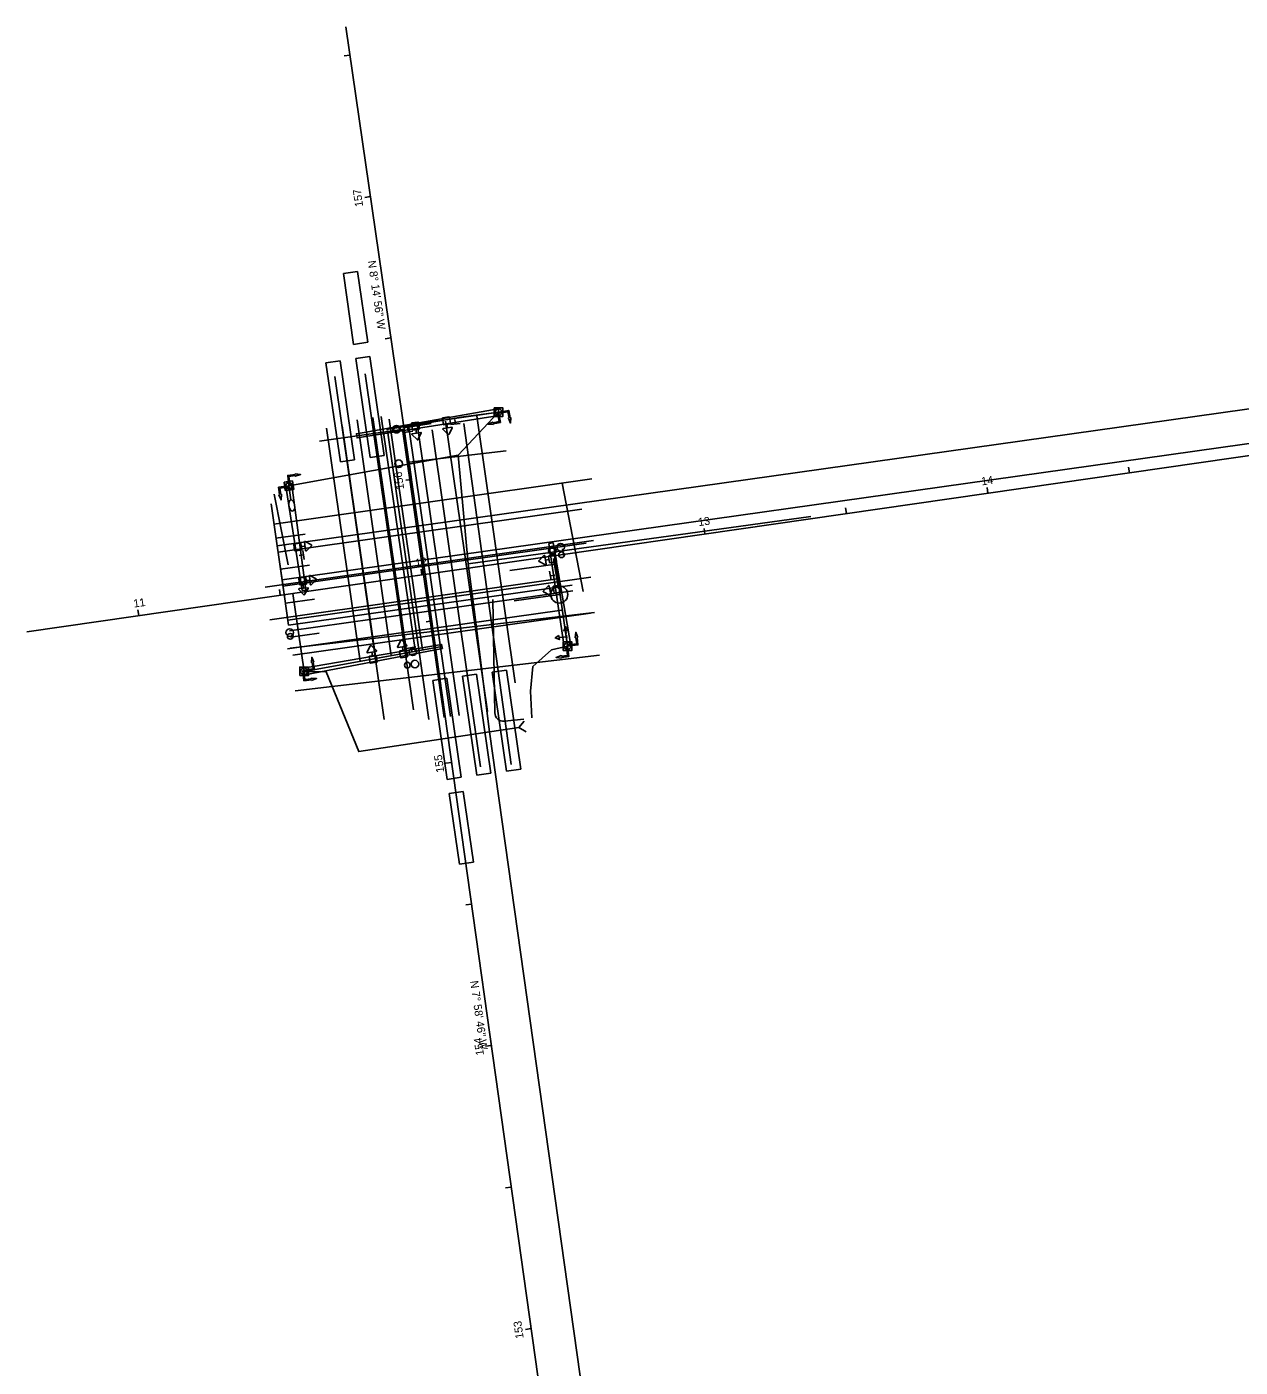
# Model space of a CAD drawing. Extents: x 1827063 to 1831280, y 711192 to 712800.
# Drawn here: x 1827917.1 to 1828341.4, y 712025.4 to 712494.3 of the extents above; entities that cross this region are included whole.
import ezdxf

# ---------------------------------------------------------------- set-up
doc = ezdxf.new("R2010")
doc.units = 0
for name, color, linetype in [('BR_P_Gen_Joint_Filler', 7, 'Continuous'), ('BR_P_Sub_Centerline', 7, 'Continuous'), ('Default', 7, 'Continuous'), ('DR_P_Cells', 7, 'Continuous'), ('DR_P_Storm_Sewer', 7, 'Continuous'), ('LT_P_Luminaires', 7, 'Continuous'), ('PV_P_Walk', 7, 'Continuous'), ('SC_Scratch6', 7, 'Continuous'), ('SG_P_Wiring', 7, 'Continuous'), ('SG_X_Detection', 7, 'Continuous'), ('SG_X_Interconnect_Cable', 7, 'Continuous'), ('TX_P_20', 7, 'Continuous'), ('UT_P_Water', 7, 'Continuous'), ('UT_P_Water_Text', 7, 'Continuous'), ('UT_X_Misc_Cells', 7, 'Continuous'), ('VG_X_Cells', 7, 'Continuous')]:
    doc.layers.add(name, color=color, linetype=linetype)

# ---------------------------------------------------------------- blocks, each defined once
blk = doc.blocks.new('SGN1P')
at = {"layer": 'UT_X_Misc_Cells'}
for p, q in [((0, 0), (-0.08, 0)), ((0, 0.08), (0, -0.08))]:
    blk.add_line(p, q, dxfattribs=at)
blk = doc.blocks.new('Sighead')
at = {"layer": 'Default'}
for p, q in [((-0.03, 0.975), (-0.335, 0.569)), ((0.335, 0.569), (0.03, 0.975)), ((-0.305, 0.508), (0.305, 0.508)), ((-0.254, -0.216), (-0.254, 0.216)), ((-0.216, 0.254), (0.216, 0.254)), ((0, 0.508), (0, 0.254)), ((0.254, 0.216), (0.254, -0.216)), ((0.216, -0.254), (-0.216, -0.254))]:
    blk.add_line(p, q, dxfattribs=at)
for centre, start, end in [((0, 0.953), 36.8699, 143.1301), ((-0.305, 0.546), 143.1301, 270), ((-0.216, 0.216), 90, 180), ((0.216, 0.216), 0, 90), ((0.305, 0.546), 270, 36.8699), ((-0.216, -0.216), 180, 270), ((0.216, -0.216), 270, 0)]:
    blk.add_arc(centre, 0.0381, start, end, dxfattribs=at)
blk = doc.blocks.new('SPOLE')
at = {"layer": 'DR_P_Cells'}
blk.add_lwpolyline([(-0.075, -0.075), (0.075, -0.075), (0.075, 0.075), (-0.075, 0.075)], close=True, dxfattribs=at)
blk.add_circle((0, 0), 0.06, dxfattribs=at)

msp = doc.modelspace()

# ---------------------------------------------------------------- linework, layer by layer
at = {"layer": 'BR_P_Gen_Joint_Filler'}
for p, q in [((1828044.52, 712274.33), (1828032.59, 712356.83)), ((1828049.96, 712275.12), (1828038.03, 712357.61)), ((1828052.93, 712275.55), (1828041, 712358.04)), ((1828057.4, 712355.81), (1828042.89, 712353.41)), ((1828055.44, 712276.31), (1828043.76, 712357.03)), ((1828068.96, 712357.7), (1828057.4, 712355.81)), ((1828063.52, 712356.41), (1828078.1, 712254.78)), ((1828082.02, 712359.5), (1828068.96, 712357.7)), ((1828074.39, 712358.22), (1828087.78, 712264.83)), ((1828033.67, 712272.37), (1828021.87, 712353.92)), ((1828039.11, 712273.16), (1828027.31, 712354.71)), ((1828043.2, 712353.03), (1828057.69, 712251.99)), ((1828062.99, 712252.68), (1828048.47, 712353.53)), ((1828050.7, 712354.28), (1828065.22, 712253)), ((1828053.66, 712354.77), (1828068.19, 712253.43)), ((1828003.47, 712320.37), (1828114.59, 712336.14)), ((1828104.23, 712334.63), (1828111.66, 712296.73)), ((1828003.59, 712330.85), (1828008.39, 712306.15)), ((1828004.91, 712310.47), (1828111.11, 712325.54)), ((1828000.42, 712298.29), (1828115.25, 712314.57)), ((1828004.19, 712315.42), (1828014.37, 712316.86)), ((1828006.63, 712298.59), (1828112.68, 712313.64)), ((1828005.77, 712304.53), (1828015.91, 712305.97)), ((1828085.97, 712304.11), (1828101.89, 712306.37)), ((1828002.03, 712286.9), (1828102.63, 712301.17)), ((1828008.35, 712286.72), (1828114.25, 712301.74)), ((1828087.48, 712293.47), (1828103.4, 712295.72)), ((1828007.49, 712292.65), (1828017.6, 712294.09)), ((1828008.24, 712276.67), (1828104.12, 712290.27)), ((1828010.13, 712274.46), (1828114.22, 712289.23)), ((1828009.21, 712280.78), (1828019.28, 712282.21))]:
    msp.add_line(p, q, dxfattribs=at)
msp.add_circle((1828103.24, 712295.7), 3, dxfattribs=at)
at = {"layer": 'BR_P_Sub_Centerline'}
for p, q in [((1828009.09, 712276.96), (1828115.54, 712289.43)), ((1828010.84, 712262.06), (1828117.28, 712274.53))]:
    msp.add_line(p, q, dxfattribs=at)
at = {"layer": 'DR_P_Storm_Sewer'}
for p, q in [((1828056.39, 712302.78), (1828028.62, 712494.31)), ((1828030.05, 712484.42), (1828028.08, 712484.13)), ((1827917.05, 712282.69), (1829201.8, 712467.95)), ((1828037.23, 712434.93), (1828035.25, 712434.65)), ((1828044.4, 712385.45), (1828042.42, 712385.16)), ((1828302.62, 712338.29), (1828302.34, 712340.27)), ((1828051.58, 712335.97), (1828049.6, 712335.68)), ((1828253.14, 712331.16), (1828252.85, 712333.13)), ((1828203.65, 712324.02), (1828203.36, 712326)), ((1828154.16, 712316.88), (1828153.87, 712318.86)), ((1828104.67, 712309.75), (1828104.39, 712311.73)), ((1828055.18, 712302.61), (1828054.9, 712304.59)), ((1828100.32, 711989.38), (1828056.39, 712302.78)), ((1828005.69, 712295.47), (1828005.41, 712297.45)), ((1827956.21, 712288.34), (1827955.92, 712290.32)), ((1828058.67, 712286.48), (1828056.69, 712286.2)), ((1828065.61, 712236.96), (1828063.63, 712236.68)), ((1828072.55, 712187.44), (1828070.57, 712187.17)), ((1828079.5, 712137.93), (1828077.51, 712137.65)), ((1828086.44, 712088.41), (1828084.46, 712088.13)), ((1828093.38, 712038.9), (1828091.4, 712038.62))]:
    msp.add_line(p, q, dxfattribs=at)
at = {"layer": 'LT_P_Luminaires'}
msp.add_line((1828008.69, 712333.77), (1828009.42, 712328.82), dxfattribs=at)
msp.add_circle((1828008.69, 712333.77), 1.1, dxfattribs=at)
msp.add_ellipse((1828009.71, 712326.84), major_axis=(0.29, -1.98), ratio=0.5, dxfattribs=at)
at = {"layer": 'PV_P_Walk'}
for p, q in [((1828004.58, 712312.75), (1828495.96, 712382.05)), ((1828006.3, 712300.88), (1828497.63, 712370.16)), ((1828024.82, 712371.95), (1828042, 712252.01)), ((1828035.35, 712372.93), (1828052.27, 712255.34)), ((1828082.02, 712359.49), (1828048.86, 712354.69)), ((1828048.96, 712353.99), (1828058.49, 712355.58)), ((1828086.47, 712236.23), (1828069.84, 712355.48)), ((1828019.39, 712349.31), (1828049.02, 712353.61)), ((1828075.74, 712235.43), (1828058.82, 712353.28)), ((1828050.71, 712341.97), (1828084.72, 712345.95)), ((1828051.58, 712335.97), (1828050.71, 712341.97)), ((1828002.45, 712327.4), (1828007.03, 712295.67)), ((1828006.3, 712300.88), (1828004.58, 712312.75)), ((1828106.15, 712277.65), (1828101.58, 712309.3)), ((1828101.21, 712308.33), (1828102.93, 712297.65)), ((1828008.6, 712285.04), (1828006.3, 712300.88)), ((1828107.76, 712299.03), (1828008.6, 712285.04)), ((1828108.04, 712297.05), (1828008.88, 712283.06)), ((1828014.02, 712268.82), (1828010.08, 712296.11)), ((1828038.95, 712273.33), (1828049.41, 712275.22))]:
    msp.add_line(p, q, dxfattribs=at)
for centre, radius in [((1828046.33, 712353.55), 1.33), ((1828046.33, 712353.55), 1), ((1828047.08, 712341.45), 1.33), ((1828103.69, 712312.26), 1.33), ((1828100.79, 712310.96), 1.33), ((1828100.79, 712310.96), 1), ((1828104.07, 712309.62), 1), ((1828008.98, 712282.4), 1.33), ((1828009.17, 712281.08), 1), ((1828052.04, 712275.69), 1.33), ((1828050.12, 712271), 1), ((1828052.76, 712271.37), 1.33)]:
    msp.add_circle(centre, radius, dxfattribs=at)
at = {"layer": 'SC_Scratch6'}
for p, q in [((1828007, 712335.04), (1828009.97, 712335.47)), ((1828007.42, 712332.07), (1828007, 712335.04)), ((1828010.4, 712332.5), (1828007.42, 712332.07)), ((1828009.97, 712335.47), (1828010.4, 712332.5))]:
    msp.add_line(p, q, dxfattribs=at)
for points in [[(1828080.52, 712357.99), (1828083.52, 712357.99), (1828083.52, 712360.99), (1828080.52, 712360.99)], [(1828104.65, 712276.15), (1828107.65, 712276.15), (1828107.65, 712279.15), (1828104.65, 712279.15)]]:
    msp.add_lwpolyline(points, close=True, dxfattribs=at)
for centre in [(1828082.02, 712359.49), (1828106.15, 712277.65)]:
    msp.add_circle(centre, 1.2, dxfattribs=at)
for start, end in [(8.182, 188.182), (188.182, 8.182)]:
    msp.add_arc((1828008.7, 712333.77), 1.09, start, end, dxfattribs=at)
at = {"layer": 'SG_P_Wiring'}
for p, q in [((1828082.22, 712358.31), (1828081.83, 712360.68)), ((1828013.81, 712270), (1828014.24, 712267.64))]:
    msp.add_line(p, q, dxfattribs=at)
at = {"layer": 'SG_X_Detection'}
for p, q in [((1828032.69, 712408.68), (1828027.74, 712407.96)), ((1828027.74, 712407.96), (1828031.34, 712383.22)), ((1828036.28, 712383.94), (1828032.69, 712408.68)), ((1828031.34, 712383.22), (1828036.28, 712383.94)), ((1828037, 712378.99), (1828032.06, 712378.27)), ((1828042.03, 712344.35), (1828037, 712378.99)), ((1828026.61, 712377.48), (1828021.66, 712376.76)), ((1828021.66, 712376.76), (1828026.69, 712342.13)), ((1828031.64, 712342.84), (1828026.61, 712377.48)), ((1828032.06, 712378.27), (1828037.08, 712343.63)), ((1828026.69, 712342.13), (1828031.64, 712342.84)), ((1828037.08, 712343.63), (1828042.03, 712344.35)), ((1828063.94, 712266.4), (1828058.99, 712265.68)), ((1828068.97, 712231.76), (1828063.94, 712266.4)), ((1828074.34, 712267.83), (1828069.39, 712267.11)), ((1828069.39, 712267.11), (1828074.42, 712232.47)), ((1828079.37, 712233.19), (1828074.34, 712267.83)), ((1828084.74, 712269.24), (1828079.8, 712268.53)), ((1828079.8, 712268.53), (1828084.82, 712233.89)), ((1828089.77, 712234.61), (1828084.74, 712269.24)), ((1828058.99, 712265.68), (1828064.02, 712231.04)), ((1828084.82, 712233.89), (1828089.77, 712234.61)), ((1828064.02, 712231.04), (1828068.97, 712231.76)), ((1828074.42, 712232.47), (1828079.37, 712233.19)), ((1828069.68, 712226.81), (1828064.74, 712226.09)), ((1828064.74, 712226.09), (1828068.33, 712201.35)), ((1828073.28, 712202.07), (1828069.68, 712226.81)), ((1828068.33, 712201.35), (1828073.28, 712202.07))]:
    msp.add_line(p, q, dxfattribs=at)
at = {"layer": 'SG_X_Interconnect_Cable'}
for p, q in [((1828071.34, 712306.41), (1828191.24, 712322.98)), ((1828120.04, 711954.39), (1828078.87, 712247.62))]:
    msp.add_line(p, q, dxfattribs=at)
msp.add_lwpolyline([(1828071.34, 712306.41), (1828073.44, 712290.52), (1828078.86, 712247.63)], dxfattribs=at)
at = {"layer": 'TX_P_20'}
for points in [[(1828082.22, 712358.31), (1828032.54, 712350.52), (1828032.3, 712351.95), (1828081.83, 712360.68)], [(1828104.97, 712277.47), (1828099.65, 712313.54), (1828101.08, 712313.77), (1828107.34, 712277.85)], [(1828013.81, 712270), (1828062.1, 712278.25), (1828062.36, 712276.83), (1828014.24, 712267.64)]]:
    msp.add_lwpolyline(points, dxfattribs=at)
at = {"layer": 'UT_P_Water'}
msp.add_line((1828067.84, 712344.47), (1828008.7, 712333.77), dxfattribs=at)
for points in [[(1828082.02, 712359.49), (1828067.84, 712344.47), (1828071.34, 712306.41)], [(1828080.71, 712254.31), (1828080.07, 712293.98)], [(1828106.15, 712277.65), (1828100.56, 712276.39), (1828094.03, 712270.57), (1828093.14, 712261.87), (1828093.62, 712252.55)], [(1828014.03, 712268.82), (1828021.75, 712268.63), (1828033.14, 712240.74), (1828078.86, 712247.63), (1828089.05, 712249.23)], [(1828090.84, 712252.13), (1828084.04, 712251.38)], [(1828090.95, 712251.38), (1828089.05, 712249.23), (1828091.7, 712247.68)]]:
    msp.add_lwpolyline(points, dxfattribs=at)
msp.add_arc((1828083.71, 712254.36), 3, 180.9244, 276.3336, dxfattribs=at)
at = {"layer": 'UT_P_Water_Text'}
for p, q in [((1828013.32, 712297.06), (1828007.62, 712333.62)), ((1828009.78, 712333.93), (1828014.64, 712297.25)), ((1828014.64, 712297.25), (1828013.32, 712297.06)), ((1828014.02, 712268.82), (1828062.22, 712277.54))]:
    msp.add_line(p, q, dxfattribs=at)
msp.add_arc((1828008.7, 712333.77), 1.09, 8.2217, 188.2217, dxfattribs=at)
at = {"layer": 'UT_X_Misc_Cells'}
for p, q in [((1828068.55, 712355.57), (1828065.37, 712355.16)), ((1828066.96, 712355.37), (1828066.76, 712356.95)), ((1828013.83, 712309.58), (1828012.25, 712309.34)), ((1828013.59, 712311.16), (1828014.07, 712308)), ((1828100.44, 712300.69), (1828099.89, 712303.84)), ((1828100.16, 712302.26), (1828101.74, 712302.53)), ((1828049.92, 712276.85), (1828053.07, 712277.38)), ((1828051.49, 712277.11), (1828051.76, 712275.54))]:
    msp.add_line(p, q, dxfattribs=at)
at = {"layer": 'VG_X_Cells'}
for p, q in [((1828081.62, 712359.42), (1828082.02, 712359.49)), ((1828082.09, 712359.1), (1828082.02, 712359.49)), ((1828009.09, 712333.82), (1828008.7, 712333.77)), ((1828008.75, 712333.38), (1828008.7, 712333.77)), ((1828103.21, 712280.66), (1828104.21, 712280.77)), ((1828104.8, 712280.83), (1828105.8, 712280.94)), ((1828105.68, 712282.03), (1828105.58, 712283.02)), ((1828105.85, 712280.44), (1828105.75, 712281.43)), ((1828105.75, 712277.6), (1828106.15, 712277.65)), ((1828106.02, 712278.85), (1828105.91, 712279.84)), ((1828106.1, 712278.05), (1828106.15, 712277.65)), ((1828106.15, 712277.65), (1828106.15, 712277.65)), ((1828013.96, 712269.22), (1828013.56, 712269.18)), ((1828013.96, 712269.22), (1828014.02, 712268.83))]:
    msp.add_line(p, q, dxfattribs=at)
for points in [[(1828082.02, 712359.49), (1828085.61, 712360.13), (1828086.06, 712357.56)], [(1828080.16, 712355.19), (1828078.22, 712355.33), (1828080.01, 712356.05), (1828080.05, 712355.82)], [(1828080.05, 712355.82), (1828082.22, 712356.22), (1828081.62, 712359.42)], [(1828082.02, 712359.49), (1828082.69, 712355.9), (1828080.12, 712355.43)], [(1828080.12, 712355.43), (1828080.16, 712355.19)], [(1828085.67, 712357.49), (1828085.29, 712359.67), (1828082.09, 712359.1)], [(1828086.3, 712357.6), (1828086.14, 712355.66), (1828085.44, 712357.45), (1828085.67, 712357.49)], [(1828086.06, 712357.56), (1828086.3, 712357.6)], [(1828008.7, 712333.77), (1828008.28, 712337.4), (1828010.87, 712337.69)], [(1828010.91, 712337.3), (1828008.72, 712337.05), (1828009.09, 712333.82)], [(1828010.87, 712337.69), (1828010.85, 712337.93)], [(1828010.85, 712337.93), (1828012.78, 712337.66), (1828010.94, 712337.06), (1828010.91, 712337.3)], [(1828008.7, 712333.77), (1828005.08, 712333.24), (1828005.47, 712330.66)], [(1828005.86, 712330.72), (1828005.54, 712332.9), (1828008.75, 712333.38)], [(1828005.23, 712330.62), (1828005.99, 712328.83), (1828006.1, 712330.76), (1828005.86, 712330.72)], [(1828005.47, 712330.66), (1828005.23, 712330.62)], [(1828109.09, 712280.6), (1828109.34, 712278.41), (1828106.1, 712278.05)], [(1828106.15, 712277.65), (1828109.78, 712278.06), (1828109.49, 712280.65)], [(1828109.72, 712280.68), (1828109.03, 712282.5), (1828108.85, 712280.58), (1828109.09, 712280.6)], [(1828109.49, 712280.65), (1828109.72, 712280.68)], [(1828103.99, 712274.09), (1828106.18, 712274.38), (1828105.75, 712277.6)], [(1828106.15, 712277.65), (1828106.63, 712274.03), (1828104.05, 712273.69)], [(1828016.84, 712271.89), (1828017.18, 712269.71), (1828013.96, 712269.22)], [(1828014.02, 712268.83), (1828017.63, 712269.37), (1828017.24, 712271.95)], [(1828017.47, 712271.99), (1828016.7, 712273.78), (1828016.61, 712271.85), (1828016.84, 712271.89)], [(1828017.24, 712271.95), (1828017.47, 712271.99)], [(1828104.08, 712273.46), (1828102.14, 712273.69), (1828103.97, 712274.32), (1828104, 712274.09)], [(1828104.05, 712273.69), (1828104.08, 712273.46)], [(1828013.56, 712269.18), (1828013.97, 712265.55), (1828016.56, 712265.84)], [(1828016.52, 712266.24), (1828014.32, 712265.99), (1828013.96, 712269.22)], [(1828016.59, 712265.61), (1828018.41, 712266.31), (1828016.49, 712266.48), (1828016.52, 712266.24)], [(1828016.56, 712265.84), (1828016.59, 712265.61)]]:
    msp.add_lwpolyline(points, dxfattribs=at)
for points in [[(1828103.14, 712281.36), (1828103.29, 712279.97), (1828101.82, 712280.51)], [(1828106.27, 712283.1), (1828104.88, 712282.95), (1828105.43, 712284.42)]]:
    msp.add_lwpolyline(points, close=True, dxfattribs=at)

# ---------------------------------------------------------------- block references
at = {"layer": 'SC_Scratch6', "xscale": 20, "yscale": 20}
msp.add_blockref('SPOLE', (1828014.02, 712268.82), dxfattribs=at)
at = {"layer": 'UT_P_Water'}
for p, xscale, yscale, rotation in [((1828052.95, 712354.65), 4.92125000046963, 4.92125000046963, -171.59372884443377), ((1828063.8, 712356.46), 4.921250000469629, 4.921250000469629, -171.35681781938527), ((1828011.82, 712312.31), 4.921250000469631, 4.921250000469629, -83.02508647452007), ((1828013.55, 712300.43), 4.921250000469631, 4.92125000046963, -173.92718958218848), ((1828013.55, 712300.43), 4.921250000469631, 4.92125000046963, -83.92718958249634)]:
    msp.add_blockref('Sighead', p, dxfattribs=dict(at, xscale=xscale, yscale=yscale, rotation=rotation))
at = {"layer": 'UT_X_Misc_Cells', "xscale": 20.000000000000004, "yscale": 20.000000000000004, "rotation": -80.53823811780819}
msp.add_blockref('SGN1P', (1828050.47, 712352.62), dxfattribs=at)
at = {"layer": 'VG_X_Cells'}
for p, xscale, yscale, rotation in [((1828100.9, 712308.18), 4.921250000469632, 4.921250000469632, 99.30421326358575), ((1828102.48, 712297.59), 4.921250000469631, 4.921250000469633, 99.46510698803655), ((1828038.13, 712273.07), 4.921250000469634, 4.921250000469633, 9.769014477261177), ((1828048.81, 712274.97), 4.921250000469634, 4.921250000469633, 9.769014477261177)]:
    msp.add_blockref('Sighead', p, dxfattribs=dict(at, xscale=xscale, yscale=yscale, rotation=rotation))

# ---------------------------------------------------------------- texts
at = {"layer": 'DR_P_Storm_Sewer'}
for s, rotation, p in [('157', 98.2489, (1828034.69, 712431.53)), ('N 8%%d 14\' 56" W', 278.2489, (1828036.26, 712412.36)), ('156', 98.2489, (1828049.03, 712332.62)), ('14', 8.2055, (1828251.03, 712333.88)), ('13', 8.2055, (1828152.01, 712319.6)), ('12', 8.2055, (1828053.06, 712305.34)), ('11', 8.2055, (1827954.55, 712291.13)), ('155', 97.9795, (1828063.05, 712233.63)), ('N 7%%d 58\' 46" W', 277.9795, (1828072.1, 712160.44)), ('154', 97.9795, (1828076.93, 712134.63)), ('153', 97.9795, (1828090.82, 712035.55))]:
    msp.add_text(s, height=2.8, rotation=rotation, dxfattribs=at).set_placement(p)

doc.saveas('drawing.dxf')
